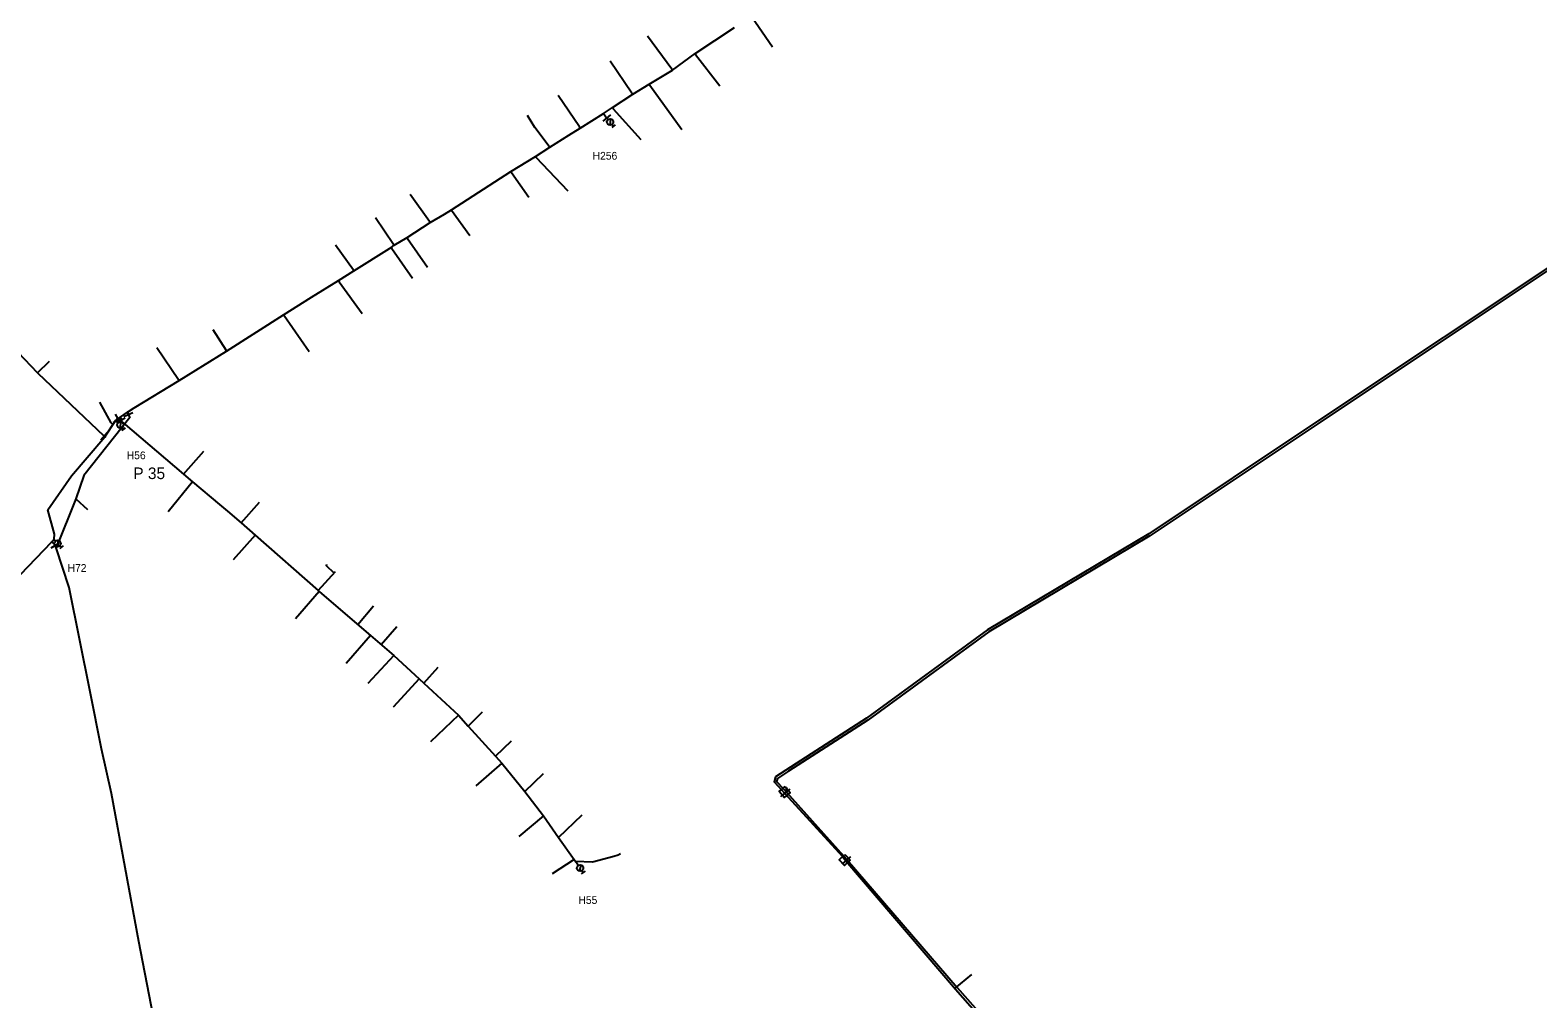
# Model space of a CAD drawing. Extents: x -548873 to -538270, y -1201997 to -1192514.
# Drawn here: x -546105.6 to -545715.2, y -1194848.6 to -1194597.8 of the extents above; entities that cross this region are included whole.
import ezdxf

# ---------------------------------------------------------------- set-up
doc = ezdxf.new("R2010")
doc.units = 0
for name, color, linetype in [('KN_HRAN_STÁTNÍ', 7, 'Continuous'), ('KN_PARC_Č', 7, 'Continuous'), ('KN_VKP_HRAN_SPORNÁ', 7, 'Continuous'), ('PK_PARC_Čv', 7, 'Continuous'), ('Vrstva 29', 7, 'Continuous'), ('Vrstva 39', 7, 'Continuous')]:
    doc.layers.add(name, color=color, linetype=linetype)

# ---------------------------------------------------------------- blocks, each defined once
blk = doc.blocks.new('160')
at = {"layer": 'KN_HRAN_STÁTNÍ'}
blk.add_circle((0, 0), 0.0458, dxfattribs=at)
blk = doc.blocks.new('147')
at = {"layer": 'KN_HRAN_STÁTNÍ'}
blk.add_line((0, 1.27), (0, -1.27), dxfattribs=at)
blk = doc.blocks.new('133')
at = {"layer": 'KN_HRAN_STÁTNÍ'}
for p, q in [((0.28, 0), (0, 0)), ((0.54, 0.58), (1.7, -0.58)), ((1.94, 0), (2.52, 0)), ((2.52, 0.58), (2.52, -0.58))]:
    blk.add_line(p, q, dxfattribs=at)
blk.add_circle((1.11, 0), 0.825, dxfattribs=at)
blk = doc.blocks.new('150')
at = {"layer": 'KN_HRAN_STÁTNÍ'}
blk.add_line((0, 1.27), (0, -1.27), dxfattribs=at)
blk = doc.blocks.new('123')
at = {"layer": 'KN_HRAN_STÁTNÍ'}
for p, q in [((-0.26, 0.96), (0.26, 0.96)), ((-0.19, 1.13), (0.19, 0.79)), ((-0.19, 0.79), (0, 0.96)), ((0, 1.22), (0, 0.96)), ((0, 0.96), (0.19, 1.13)), ((0, 0.96), (0, 0))]:
    blk.add_line(p, q, dxfattribs=at)

msp = doc.modelspace()

# ---------------------------------------------------------------- linework, layer by layer
at = {"layer": 'KN_PARC_Č'}
for points in [[(-545918.828, -1194594.156), (-545918.68, -1194594.37), (-545913.356, -1194602.146)], [(-545939.3, -1194608.11), (-545939.46, -1194607.92), (-545945.707, -1194599.362)], [(-545949.56, -1194614.35), (-545949.75, -1194614.15), (-545955.413, -1194605.808)], [(-545933.42, -1194603.82), (-545933.28, -1194604.1), (-545927.022, -1194612.211)], [(-545945.3, -1194611.79), (-545945.17, -1194612.08), (-545936.824, -1194623.508)], [(-545963.16, -1194623.13), (-545963.37, -1194622.86), (-545968.86, -1194614.719)], [(-545954.79, -1194617.85), (-545954.65, -1194618.13), (-545947.435, -1194626.078)], [(-545971.04, -1194628.1), (-545971.172, -1194627.885), (-545974.882, -1194623.002), (-545976.825, -1194619.899)], [(-545974.77, -1194630.49), (-545974.62, -1194630.72), (-545966.33, -1194639.439)], [(-545981.12, -1194634.42), (-545980.968, -1194634.61), (-545976.491, -1194641.038)], [(-546002.01, -1194647.63), (-546002.15, -1194647.38), (-546007.181, -1194640.325)], [(-545996.53, -1194644.31), (-545996.45, -1194644.38), (-545991.745, -1194650.929)], [(-546011.34, -1194653.51), (-546011.52, -1194653.26), (-546016.155, -1194646.353)], [(-546021.78, -1194660.12), (-546021.9, -1194659.9), (-546026.486, -1194653.458)], [(-546007.99, -1194651.47), (-546007.85, -1194651.72), (-546002.697, -1194659.192)], [(-546012.1, -1194654.03), (-546012.05, -1194654.15), (-546012, -1194654.24), (-546011.96, -1194654.31), (-546006.612, -1194661.976)], [(-546025.74, -1194662.64), (-546025.61, -1194662.94), (-546019.635, -1194671.126)], [(-546040.02, -1194671.47), (-546039.85, -1194671.72), (-546033.312, -1194681.026)], [(-546054.77, -1194680.9), (-546054.88, -1194680.67), (-546058.211, -1194675.412)], [(-546067.046, -1194688.525), (-546067.19, -1194688.32), (-546072.795, -1194680.069)], [(-546103.668, -1194686.508), (-546100.615, -1194683.539)], [(-546084.156, -1194699.903), (-546084.64, -1194699.48), (-546087.528, -1194694.128)], [(-546065.858, -1194712.746), (-546060.602, -1194706.805)], [(-546063.532, -1194714.728), (-546069.839, -1194722.484)], [(-546093.764, -1194719.121), (-546090.761, -1194721.944)], [(-546050.998, -1194725.378), (-546046.231, -1194720.044)], [(-546047.3, -1194728.521), (-546053.048, -1194734.966)], [(-546030.999, -1194742.895), (-546026.531, -1194737.99)], [(-546026.868, -1194738.36), (-546028.872, -1194736.493), (-546028.809, -1194736.037)], [(-546030.747, -1194743.114), (-546036.883, -1194750.242)], [(-546020.784, -1194751.663), (-546016.692, -1194746.836)], [(-546017.427, -1194754.543), (-546023.798, -1194761.803)], [(-546014.67, -1194756.892), (-546010.613, -1194752.229)], [(-546011.393, -1194759.683), (-546018.176, -1194766.976)], [(-546003.678, -1194766.869), (-545999.928, -1194762.746)], [(-546004.848, -1194765.782), (-546011.562, -1194773.105)], [(-545992.133, -1194778.009), (-545988.453, -1194774.273)], [(-545994.69, -1194775.19), (-546001.912, -1194782.098)], [(-545985.073, -1194785.791), (-545980.938, -1194781.821)], [(-545983.497, -1194787.614), (-545990.194, -1194793.458)], [(-545977.492, -1194794.925), (-545972.654, -1194790.305)], [(-545972.702, -1194801.27), (-545979.011, -1194806.556)], [(-545968.742, -1194806.853), (-545962.637, -1194800.991)], [(-545964.714, -1194812.532), (-545970.431, -1194816.292)], [(-545964.391, -1194812.998), (-545959.943, -1194813.184), (-545954.451, -1194811.677), (-545953.343, -1194811.296), (-545952.722, -1194810.98)], [(-545866.186, -1194845.929), (-545861.776, -1194842.309)]]:
    msp.add_lwpolyline(points, dxfattribs=at)
at = {"layer": 'KN_VKP_HRAN_SPORNÁ'}
for points in [[(-546080.39, -1194696.7), (-546078.63, -1194695.63), (-546067.046, -1194688.525), (-546054.77, -1194680.9), (-546040.02, -1194671.47), (-546032.726, -1194666.96), (-546025.74, -1194662.64), (-546021.78, -1194660.12), (-546012.55, -1194654.3), (-546012.1, -1194654.03), (-546011.34, -1194653.51), (-546007.99, -1194651.47), (-546002.01, -1194647.63), (-545998.343, -1194645.409), (-545996.53, -1194644.31), (-545981.12, -1194634.42), (-545974.77, -1194630.49), (-545971.04, -1194628.1), (-545966.109, -1194624.99), (-545963.16, -1194623.13), (-545957.14, -1194619.34), (-545954.79, -1194617.85), (-545949.56, -1194614.35), (-545945.3, -1194611.79), (-545939.3, -1194608.11), (-545933.42, -1194603.82), (-545923.164, -1194597.128)], [(-545660.184, -1194623.128), (-545660.83, -1194624.146), (-545706.918, -1194655.511), (-545772.196, -1194699.02), (-545815.93, -1194728.206), (-545857.666, -1194753.1), (-545888.99, -1194775.992), (-545912.587, -1194791.148), (-545912.96, -1194792.429), (-545911.06, -1194794.49), (-545910.261, -1194795.367)], [(-545659.726, -1194623.527), (-545660.39, -1194624.574), (-545706.583, -1194656.009), (-545771.863, -1194699.519), (-545815.61, -1194728.714), (-545857.335, -1194753.601), (-545888.651, -1194776.487), (-545909.247, -1194789.715), (-545912.074, -1194791.531), (-545912.301, -1194792.311), (-545910.5, -1194794.25), (-545909.751, -1194795.086)], [(-546086.47, -1194702.96), (-546103.514, -1194686.669), (-546103.668, -1194686.508), (-546121.816, -1194667.569), (-546135.992, -1194653.742), (-546143.948, -1194645.105), (-546159.838, -1194627.61)], [(-546080.18, -1194697.32), (-546079.766, -1194698.106), (-546091.68, -1194713.14), (-546093.764, -1194719.121), (-546098.848, -1194731.817)], [(-546086.246, -1194703.137), (-546083.43, -1194698.78), (-546083.16, -1194698.52), (-546082.86, -1194698.35)], [(-546082.86, -1194698.35), (-546082.38, -1194698.07)], [(-546082.38, -1194698.07), (-546080.39, -1194696.7)], [(-546082.38, -1194698.07), (-546082.1, -1194698.78)], [(-546082.1, -1194698.78), (-546081.6, -1194699.41), (-546065.858, -1194712.747), (-546063.532, -1194714.728), (-546056.578, -1194720.636), (-546054.535, -1194722.373), (-546050.997, -1194725.379), (-546047.299, -1194728.521), (-546031.004, -1194742.891), (-546030.743, -1194743.118), (-546025.823, -1194747.34), (-546017.431, -1194754.54), (-546011.395, -1194759.681), (-546004.865, -1194765.767), (-546003.678, -1194766.869), (-545994.689, -1194775.191), (-545992.132, -1194778.01), (-545985.073, -1194785.791), (-545983.496, -1194787.615), (-545977.512, -1194794.898), (-545972.703, -1194801.27), (-545968.742, -1194806.853), (-545964.714, -1194812.532), (-545964.304, -1194813.124), (-545964.153, -1194813.309)], [(-546080.39, -1194696.7), (-546080.18, -1194697.32)], [(-546099.982, -1194730.283), (-546099.34, -1194729.62), (-546099.32, -1194728.33), (-546101.02, -1194722.01), (-546094.9, -1194713.16), (-546090.816, -1194708.43), (-546086.246, -1194703.137)], [(-546086.246, -1194703.137), (-546086.47, -1194702.96)], [(-546108.134, -1194738.726), (-546099.982, -1194730.283)], [(-546099.045, -1194731.205), (-546099.982, -1194730.283)], [(-546098.848, -1194731.817), (-546099.045, -1194731.205)], [(-546067.805, -1194883.685), (-546067.89, -1194883.26), (-546077.43, -1194833.78), (-546084.52, -1194795.48), (-546087.16, -1194783.85), (-546090.065, -1194769.166), (-546095.527, -1194742.126), (-546098.848, -1194731.817)], [(-545910.261, -1194795.367), (-545895.28, -1194811.81), (-545894.391, -1194812.852)], [(-545909.751, -1194795.086), (-545894.96, -1194811.58), (-545894.06, -1194812.626)], [(-545894.391, -1194812.852), (-545866.018, -1194846.126), (-545838.072, -1194877.812), (-545797.202, -1194924.152), (-545788.773, -1194934.13), (-545784.091, -1194940.448), (-545767.845, -1194984.478), (-545759.317, -1195002.13), (-545724.061, -1195067.122), (-545724.067, -1195070.605), (-545743.894, -1195096.929)], [(-545894.06, -1194812.626), (-545865.565, -1194845.732), (-545796.532, -1194923.714), (-545788.176, -1194933.597), (-545783.406, -1194940.035), (-545767.09, -1194984.214), (-545758.601, -1195001.771), (-545723.485, -1195066.954), (-545723.38, -1195070.726), (-545743.101, -1195097.708), (-545744.07, -1195099.034), (-545744.39, -1195099.646)]]:
    msp.add_lwpolyline(points, dxfattribs=at)
at = {"layer": 'PK_PARC_Čv'}
for points in [[(-545957.14, -1194619.34), (-545956.28, -1194620.54), (-545956.13, -1194620.72)], [(-546083.16, -1194698.52), (-546083.01, -1194698.84), (-546082.87, -1194699.05)], [(-546099.444, -1194729.728), (-546099.245, -1194729.93)], [(-545910.061, -1194793.655), (-545908.796, -1194795.204), (-545910.345, -1194796.469), (-545911.613, -1194794.922), (-545910.061, -1194793.655)], [(-545964.153, -1194813.309), (-545963.809, -1194813.837)], [(-545894.62, -1194811.29), (-545893.248, -1194812.745), (-545894.703, -1194814.117), (-545896.075, -1194812.662), (-545894.62, -1194811.29)]]:
    msp.add_lwpolyline(points, dxfattribs=at)

# ---------------------------------------------------------------- block references
for name, p, xscale, yscale, rotation in [('150', (-545956.28, -1194620.54), 1.000000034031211, 1.0000000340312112, -51.999999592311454), ('133', (-545956.13, -1194620.72), 1.0000000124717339, 1.0000000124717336, -49.99999868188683), ('150', (-546083.01, -1194698.84), 0.9999999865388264, 0.9999999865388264, -59.99999955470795), ('133', (-546082.87, -1194699.05), 0.9999999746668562, 0.999999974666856, -55.999999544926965), ('133', (-546099.245, -1194729.93), 0.999999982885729, 0.9999999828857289, -45), ('133', (-545963.809, -1194813.837), 0.9999999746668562, 0.999999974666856, -55.999999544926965)]:
    msp.add_blockref(name, p, dxfattribs=dict(at, xscale=xscale, yscale=yscale, rotation=rotation))
at = {"layer": 'Vrstva 29'}
for name, p, xscale, yscale, rotation in [('147', (-546082.86, -1194698.35), 0.9999999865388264, 0.9999999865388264, -149.99999955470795), ('147', (-546082.1, -1194698.78), 0.9999999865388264, 0.9999999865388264, 120.00000044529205), ('160', (-546082.38, -1194698.07), 0.9999999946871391, 0.9999999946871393, 73.99999975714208), ('147', (-546080.18, -1194697.32), 0.9999999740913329, 0.9999999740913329, 114.00000060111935), ('160', (-546080.39, -1194696.7), 0.9999999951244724, 0.9999999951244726, -146.99999872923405), ('147', (-546086.47, -1194702.96), 1.0000000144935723, 1.0000000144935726, 139.00000089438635), ('160', (-546086.246, -1194703.137), 0.9999999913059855, 0.9999999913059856, -127.00000193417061), ('147', (-546099.045, -1194731.205), 0.9999999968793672, 0.9999999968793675, 122.00000027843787), ('160', (-546099.982, -1194730.283), 1.0000000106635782, 1.0000000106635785, -134.00000165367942), ('160', (-546098.848, -1194731.817), 1.000000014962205, 1.0000000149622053, 179.0000000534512), ('147', (-545910.261, -1194795.367), 1.00000000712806, 1.00000000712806, 133.00000056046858), ('147', (-545909.751, -1194795.086), 1.0000000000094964, 1.0000000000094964, 132.0000013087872), ('160', (-545964.153, -1194813.309), 1.0000000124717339, 1.0000000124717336, 130.0000013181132), ('147', (-545894.391, -1194812.852), 1.0000000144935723, 1.0000000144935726, -49.00000089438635), ('147', (-545894.06, -1194812.626), 1.0000000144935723, 1.0000000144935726, 130.99999910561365)]:
    msp.add_blockref(name, p, dxfattribs=dict(at, xscale=xscale, yscale=yscale, rotation=rotation))
at = {"layer": 'Vrstva 39'}
msp.add_blockref('123', (-545909.751, -1194795.086), dxfattribs=at)

# ---------------------------------------------------------------- texts
at = {"layer": 'PK_PARC_Čv'}
for s, height, p in [('H256', 2, (-545959.95, -1194631.32)), ('H56', 2, (-546080.59, -1194708.89)), ('P 35', 3, (-546078.9, -1194714.04)), ('H72', 2, (-546095.915, -1194738.06)), ('H55', 2, (-545963.629, -1194824.047))]:
    msp.add_text(s, height=height, dxfattribs=at).set_placement(p)

doc.saveas('drawing.dxf')
